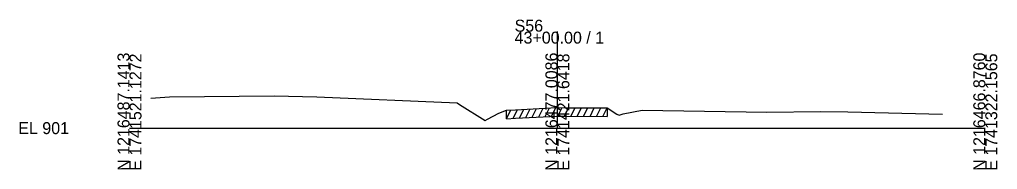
# Model space of a CAD drawing. Extents: x -26 to 1203, y -10 to 19541.
# Drawn here: x -25.7 to 202.8, y 17990.3 to 18025.4 of the extents above; entities that cross this region are included whole.
import ezdxf

# ---------------------------------------------------------------- set-up
doc = ezdxf.new("R2010")
doc.units = 0
for name, color, linetype in [('RD_GPK_XS_Cell', 7, 'Continuous'), ('RD_XS_ExGround', 7, 'Continuous'), ('RD_XS_ExPaveRet', 7, 'Continuous'), ('RD_XS_TX_Elev_EX', 7, 'Continuous')]:
    doc.layers.add(name, color=color, linetype=linetype)

msp = doc.modelspace()

# ---------------------------------------------------------------- linework, layer by layer
at = {"layer": 'RD_GPK_XS_Cell'}
for p, q in [((100, 18000), (100, 18022.6)), ((0, 18000), (100, 18000)), ((100, 18000), (200, 18000))]:
    msp.add_line(p, q, dxfattribs=at)
at = {"layer": 'RD_XS_ExGround'}
msp.add_lwpolyline([(4.96, 18007), (9.34, 18007.34), (33.79, 18007.53), (43.77, 18007.34), (76.54, 18005.94), (77.11, 18005.57), (83.12, 18001.8), (83.67, 18002.13), (86.34, 18003.48), (88.13, 18004.2), (90.19, 18004.32), (99.86, 18004.83), (102.12, 18004.79), (111.64, 18004.73), (113.93, 18003.29), (114.47, 18003.03), (115.34, 18003.33), (119.78, 18004.23), (148.97, 18003.76), (161.46, 18003.9), (167.85, 18003.81), (189.97, 18003.26)], dxfattribs=at)
at = {"layer": 'RD_XS_ExPaveRet'}
for p, q in [((88.13, 18002.2), (89.15, 18004.26)), ((88.13, 18002.2), (88.13, 18004.2)), ((89.63, 18002.29), (90.65, 18004.35)), ((91.13, 18002.37), (92.15, 18004.42)), ((92.63, 18002.45), (93.65, 18004.5)), ((94.13, 18002.53), (95.15, 18004.58)), ((95.63, 18002.61), (96.65, 18004.66)), ((97.13, 18002.69), (98.15, 18004.74)), ((98.63, 18002.76), (99.65, 18004.82)), ((100.13, 18002.82), (101.12, 18004.81)), ((101.63, 18002.8), (102.62, 18004.79)), ((103.13, 18002.79), (104.12, 18004.78)), ((104.63, 18002.78), (105.62, 18004.77)), ((106.13, 18002.77), (107.12, 18004.76)), ((107.63, 18002.76), (108.62, 18004.75)), ((109.13, 18002.75), (110.12, 18004.74)), ((110.63, 18002.74), (111.62, 18004.73)), ((111.64, 18004.73), (111.64, 18002.73)), ((88.13, 18002.2), (90.19, 18002.32)), ((90.19, 18002.32), (99.86, 18002.83)), ((99.86, 18002.83), (102.12, 18002.79)), ((102.12, 18002.79), (111.64, 18002.73))]:
    msp.add_line(p, q, dxfattribs=at)

# ---------------------------------------------------------------- texts
at = {"layer": 'RD_GPK_XS_Cell'}
for s, p in [('S56', (90, 18022.6)), ('43+00.00 / 1', (90, 18019.8)), ('EL 901', (-26, 17998.6))]:
    msp.add_text(s, height=2.8, dxfattribs=at).set_placement(p)
for s, p in [('N 1216487.1413', (0, 17990)), ('N 1216477.0086', (100, 17990)), ('N 1216466.8760', (200, 17990)), ('E 1741521.1272', (2.8, 17990)), ('E 1741421.6418', (102.8, 17990)), ('E 1741322.1565', (202.8, 17990))]:
    msp.add_text(s, height=2.8, rotation=90, dxfattribs=at).set_placement(p)
at = {"layer": 'RD_XS_TX_Elev_EX'}
msp.add_text('903.41', height=0.1, rotation=90, dxfattribs=at).set_placement((100.1, 18004.83))

doc.saveas('drawing.dxf')
